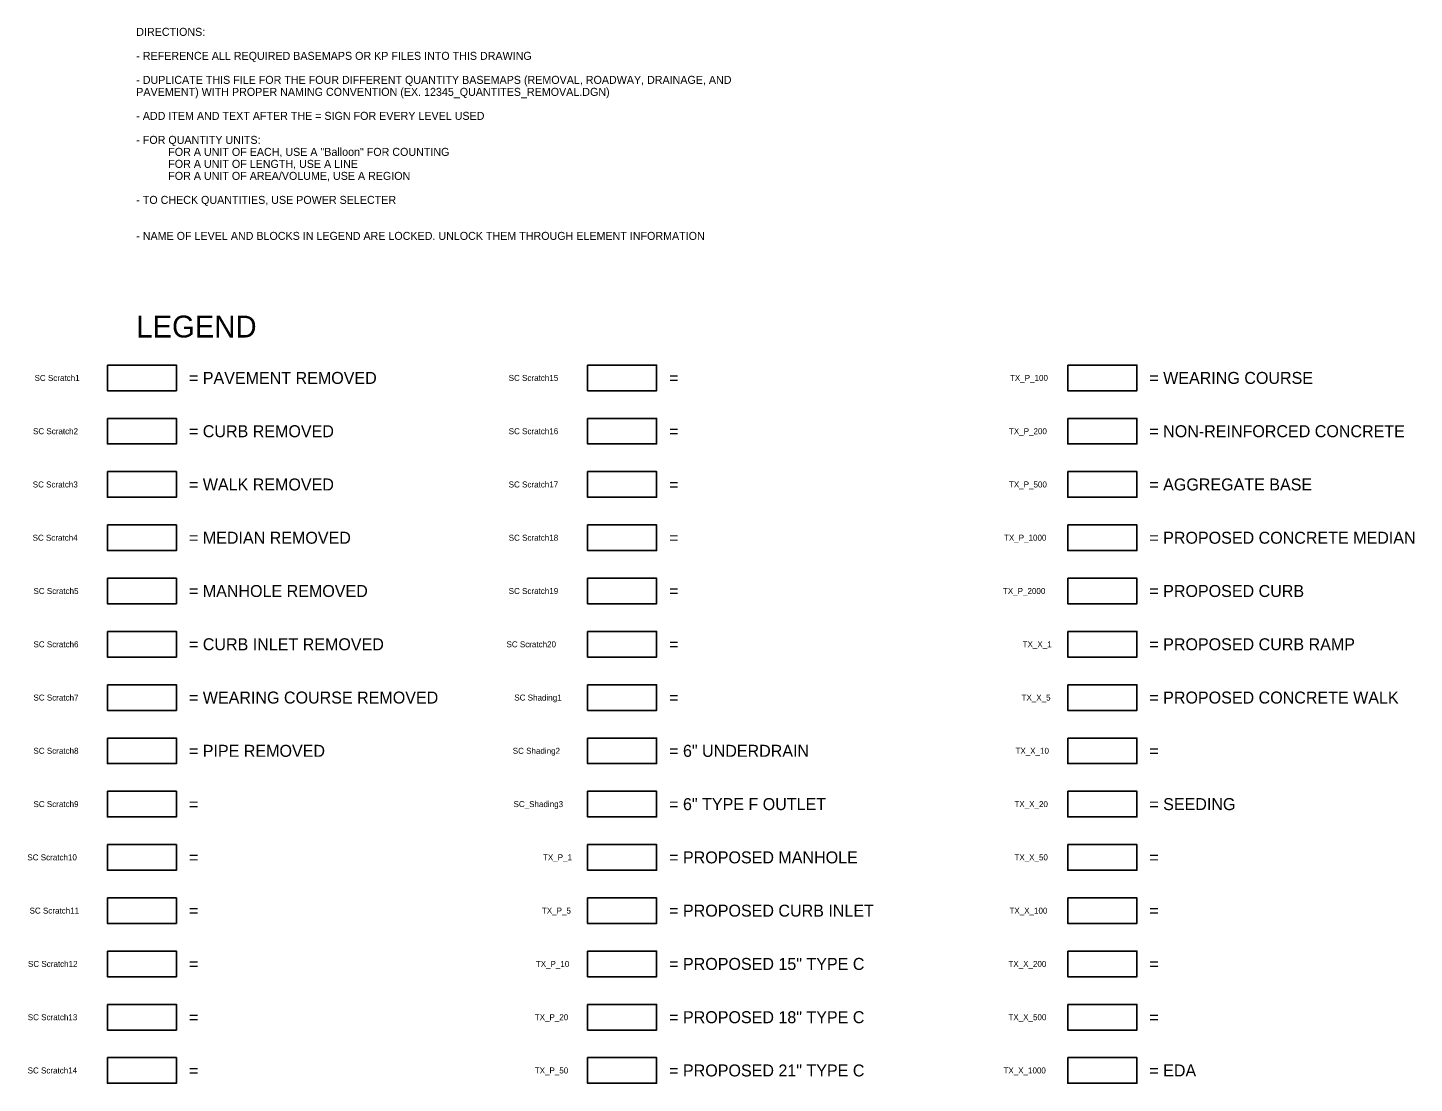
# Model space of a CAD drawing. Extents: x 2139208 to 2141645, y 639785 to 640325.
# Drawn here: x 2140935 to 2141645, y 639785 to 640325 of the extents above; entities that cross this region are included whole.
import ezdxf

# ---------------------------------------------------------------- set-up
doc = ezdxf.new("R2010")
doc.units = 0
for name, color, linetype in [('_CIVIL_CONSTRUCTION', 7, 'Continuous'), ('Default', 7, 'Continuous'), ('GE_X_Alignment', 7, 'Continuous'), ('GE_X_Alignment_100_Bearings', 7, 'Continuous'), ('GE_X_Alignment_100_Cardinal_Points', 7, 'Continuous'), ('GE_X_Alignment_100_Curve_Data', 7, 'Continuous'), ('GE_X_Alignment_100_Distances', 7, 'Continuous'), ('GE_X_Alignment_100_Stations', 7, 'Continuous'), ('PF_X_Ground_Line', 7, 'Continuous'), ('RW_X_CL', 7, 'Continuous'), ('RW_X_CL_100_Cardinal_Points', 7, 'Continuous'), ('RW_X_CL_100_Curve_Data', 7, 'Continuous'), ('RW_X_CL_100_Stations', 7, 'Continuous'), ('SC_Scratch1', 7, 'Continuous'), ('SC_Scratch10', 7, 'Continuous'), ('SC_Scratch11', 7, 'Continuous'), ('SC_Scratch12', 7, 'Continuous'), ('SC_Scratch13', 7, 'Continuous'), ('SC_Scratch14', 7, 'Continuous'), ('SC_Scratch15', 7, 'Continuous'), ('SC_Scratch16', 7, 'Continuous'), ('SC_Scratch17', 7, 'Continuous'), ('SC_Scratch18', 7, 'Continuous'), ('SC_Shading1', 7, 'Continuous'), ('TX_P_1', 7, 'Continuous'), ('TX_P_10', 7, 'Continuous'), ('TX_P_100', 7, 'Continuous'), ('TX_P_1000', 7, 'Continuous'), ('TX_P_20', 7, 'Continuous'), ('TX_P_200', 7, 'Continuous'), ('TX_P_2000', 7, 'Continuous'), ('TX_P_5', 7, 'Continuous'), ('TX_P_50', 7, 'Continuous'), ('TX_P_500', 7, 'Continuous'), ('TX_X_1', 7, 'Continuous'), ('TX_X_10', 7, 'Continuous'), ('TX_X_100', 7, 'Continuous'), ('TX_X_1000', 7, 'Continuous'), ('TX_X_20', 7, 'Continuous'), ('TX_X_200', 7, 'Continuous'), ('TX_X_5', 7, 'Continuous'), ('TX_X_50', 7, 'Continuous'), ('TX_X_500', 7, 'Continuous')]:
    doc.layers.add(name, color=color, linetype=linetype)

msp = doc.modelspace()

# ---------------------------------------------------------------- linework, layer by layer
at = {"layer": '_CIVIL_CONSTRUCTION'}
msp.add_lwpolyline([(2140976.05, 640152.46), (2141011.4, 640152.46), (2141011.4, 640139.35), (2140976.05, 640139.35)], close=True, dxfattribs=at)
at = {"layer": 'GE_X_Alignment'}
msp.add_lwpolyline([(2140976.05, 639934.31), (2141011.4, 639934.31), (2141011.4, 639921.2), (2140976.05, 639921.2)], close=True, dxfattribs=at)
at = {"layer": 'GE_X_Alignment_100_Bearings'}
msp.add_lwpolyline([(2141221.81, 639961.58), (2141257.16, 639961.58), (2141257.16, 639948.47), (2141221.81, 639948.47)], close=True, dxfattribs=at)
at = {"layer": 'GE_X_Alignment_100_Cardinal_Points'}
msp.add_lwpolyline([(2140976.05, 640070.65), (2141011.4, 640070.65), (2141011.4, 640057.54), (2140976.05, 640057.54)], close=True, dxfattribs=at)
at = {"layer": 'GE_X_Alignment_100_Curve_Data'}
msp.add_lwpolyline([(2140976.05, 640043.38), (2141011.4, 640043.38), (2141011.4, 640030.27), (2140976.05, 640030.27)], close=True, dxfattribs=at)
at = {"layer": 'GE_X_Alignment_100_Distances'}
msp.add_lwpolyline([(2141221.81, 640016.12), (2141257.16, 640016.12), (2141257.16, 640003), (2141221.81, 640003)], close=True, dxfattribs=at)
at = {"layer": 'GE_X_Alignment_100_Stations'}
msp.add_lwpolyline([(2141221.81, 639934.31), (2141257.16, 639934.31), (2141257.16, 639921.2), (2141221.81, 639921.2)], close=True, dxfattribs=at)
at = {"layer": 'PF_X_Ground_Line'}
msp.add_lwpolyline([(2141221.81, 640043.38), (2141257.16, 640043.38), (2141257.16, 640030.27), (2141221.81, 640030.27)], close=True, dxfattribs=at)
at = {"layer": 'RW_X_CL'}
msp.add_lwpolyline([(2140976.05, 640097.92), (2141011.4, 640097.92), (2141011.4, 640084.81), (2140976.05, 640084.81)], close=True, dxfattribs=at)
at = {"layer": 'RW_X_CL_100_Cardinal_Points'}
msp.add_lwpolyline([(2140976.05, 640016.12), (2141011.4, 640016.12), (2141011.4, 640003), (2140976.05, 640003)], close=True, dxfattribs=at)
at = {"layer": 'RW_X_CL_100_Curve_Data'}
msp.add_lwpolyline([(2140976.05, 639988.85), (2141011.4, 639988.85), (2141011.4, 639975.73), (2140976.05, 639975.73)], close=True, dxfattribs=at)
at = {"layer": 'RW_X_CL_100_Stations'}
msp.add_lwpolyline([(2140976.05, 639961.58), (2141011.4, 639961.58), (2141011.4, 639948.47), (2140976.05, 639948.47)], close=True, dxfattribs=at)
at = {"layer": 'SC_Scratch1'}
msp.add_lwpolyline([(2140976.05, 640125.19), (2141011.4, 640125.19), (2141011.4, 640112.08), (2140976.05, 640112.08)], close=True, dxfattribs=at)
at = {"layer": 'SC_Scratch10'}
msp.add_lwpolyline([(2140976.05, 639907.04), (2141011.4, 639907.04), (2141011.4, 639893.93), (2140976.05, 639893.93)], close=True, dxfattribs=at)
at = {"layer": 'SC_Scratch11'}
msp.add_lwpolyline([(2140976.05, 639879.77), (2141011.4, 639879.77), (2141011.4, 639866.66), (2140976.05, 639866.66)], close=True, dxfattribs=at)
at = {"layer": 'SC_Scratch12'}
msp.add_lwpolyline([(2140976.05, 639852.5), (2141011.4, 639852.5), (2141011.4, 639839.39), (2140976.05, 639839.39)], close=True, dxfattribs=at)
at = {"layer": 'SC_Scratch13'}
msp.add_lwpolyline([(2140976.05, 639825.24), (2141011.4, 639825.24), (2141011.4, 639812.12), (2140976.05, 639812.12)], close=True, dxfattribs=at)
at = {"layer": 'SC_Scratch14'}
msp.add_lwpolyline([(2140976.05, 639797.97), (2141011.4, 639797.97), (2141011.4, 639784.86), (2140976.05, 639784.86)], close=True, dxfattribs=at)
at = {"layer": 'SC_Scratch15'}
msp.add_lwpolyline([(2141221.81, 640152.46), (2141257.16, 640152.46), (2141257.16, 640139.35), (2141221.81, 640139.35)], close=True, dxfattribs=at)
at = {"layer": 'SC_Scratch16'}
msp.add_lwpolyline([(2141221.81, 640125.19), (2141257.16, 640125.19), (2141257.16, 640112.08), (2141221.81, 640112.08)], close=True, dxfattribs=at)
at = {"layer": 'SC_Scratch17'}
msp.add_lwpolyline([(2141221.81, 640097.92), (2141257.16, 640097.92), (2141257.16, 640084.81), (2141221.81, 640084.81)], close=True, dxfattribs=at)
at = {"layer": 'SC_Scratch18'}
msp.add_lwpolyline([(2141221.81, 640070.65), (2141257.16, 640070.65), (2141257.16, 640057.54), (2141221.81, 640057.54)], close=True, dxfattribs=at)
at = {"layer": 'SC_Shading1'}
msp.add_lwpolyline([(2141221.81, 639988.85), (2141257.16, 639988.85), (2141257.16, 639975.73), (2141221.81, 639975.73)], close=True, dxfattribs=at)
at = {"layer": 'TX_P_1'}
msp.add_lwpolyline([(2141221.81, 639907.04), (2141257.16, 639907.04), (2141257.16, 639893.93), (2141221.81, 639893.93)], close=True, dxfattribs=at)
at = {"layer": 'TX_P_10'}
msp.add_lwpolyline([(2141221.81, 639852.5), (2141257.16, 639852.5), (2141257.16, 639839.39), (2141221.81, 639839.39)], close=True, dxfattribs=at)
at = {"layer": 'TX_P_100'}
msp.add_lwpolyline([(2141467.57, 640152.46), (2141502.92, 640152.46), (2141502.92, 640139.35), (2141467.57, 640139.35)], close=True, dxfattribs=at)
at = {"layer": 'TX_P_1000'}
msp.add_lwpolyline([(2141467.57, 640070.65), (2141502.92, 640070.65), (2141502.92, 640057.54), (2141467.57, 640057.54)], close=True, dxfattribs=at)
at = {"layer": 'TX_P_20'}
msp.add_lwpolyline([(2141221.81, 639825.24), (2141257.16, 639825.24), (2141257.16, 639812.12), (2141221.81, 639812.12)], close=True, dxfattribs=at)
at = {"layer": 'TX_P_200'}
msp.add_lwpolyline([(2141467.57, 640125.19), (2141502.92, 640125.19), (2141502.92, 640112.08), (2141467.57, 640112.08)], close=True, dxfattribs=at)
at = {"layer": 'TX_P_2000'}
msp.add_lwpolyline([(2141467.57, 640043.38), (2141502.92, 640043.38), (2141502.92, 640030.27), (2141467.57, 640030.27)], close=True, dxfattribs=at)
at = {"layer": 'TX_P_5'}
msp.add_lwpolyline([(2141221.81, 639879.77), (2141257.16, 639879.77), (2141257.16, 639866.66), (2141221.81, 639866.66)], close=True, dxfattribs=at)
at = {"layer": 'TX_P_50'}
msp.add_lwpolyline([(2141221.81, 639797.97), (2141257.16, 639797.97), (2141257.16, 639784.86), (2141221.81, 639784.86)], close=True, dxfattribs=at)
at = {"layer": 'TX_P_500'}
msp.add_lwpolyline([(2141467.57, 640097.92), (2141502.92, 640097.92), (2141502.92, 640084.81), (2141467.57, 640084.81)], close=True, dxfattribs=at)
at = {"layer": 'TX_X_1'}
msp.add_lwpolyline([(2141467.57, 640016.12), (2141502.92, 640016.12), (2141502.92, 640003), (2141467.57, 640003)], close=True, dxfattribs=at)
at = {"layer": 'TX_X_10'}
msp.add_lwpolyline([(2141467.57, 639961.58), (2141502.92, 639961.58), (2141502.92, 639948.47), (2141467.57, 639948.47)], close=True, dxfattribs=at)
at = {"layer": 'TX_X_100'}
msp.add_lwpolyline([(2141467.57, 639879.77), (2141502.92, 639879.77), (2141502.92, 639866.66), (2141467.57, 639866.66)], close=True, dxfattribs=at)
at = {"layer": 'TX_X_1000'}
msp.add_lwpolyline([(2141467.57, 639797.97), (2141502.92, 639797.97), (2141502.92, 639784.86), (2141467.57, 639784.86)], close=True, dxfattribs=at)
at = {"layer": 'TX_X_20'}
msp.add_lwpolyline([(2141467.57, 639934.31), (2141502.92, 639934.31), (2141502.92, 639921.2), (2141467.57, 639921.2)], close=True, dxfattribs=at)
at = {"layer": 'TX_X_200'}
msp.add_lwpolyline([(2141467.57, 639852.5), (2141502.92, 639852.5), (2141502.92, 639839.39), (2141467.57, 639839.39)], close=True, dxfattribs=at)
at = {"layer": 'TX_X_5'}
msp.add_lwpolyline([(2141467.57, 639988.85), (2141502.92, 639988.85), (2141502.92, 639975.73), (2141467.57, 639975.73)], close=True, dxfattribs=at)
at = {"layer": 'TX_X_50'}
msp.add_lwpolyline([(2141467.57, 639907.04), (2141502.92, 639907.04), (2141502.92, 639893.93), (2141467.57, 639893.93)], close=True, dxfattribs=at)
at = {"layer": 'TX_X_500'}
msp.add_lwpolyline([(2141467.57, 639825.24), (2141502.92, 639825.24), (2141502.92, 639812.12), (2141467.57, 639812.12)], close=True, dxfattribs=at)

# ---------------------------------------------------------------- texts
at = {"layer": '_CIVIL_CONSTRUCTION'}
msp.add_text('SC Scratch1', height=3.072, dxfattribs=at).set_placement((2140938.76, 640144.37))
at = {"layer": 'Default'}
for s, height, p in [('DIRECTIONS:', 4.096, (2140990.82, 640321)), ('- REFERENCE ALL REQUIRED BASEMAPS OR KP FILES INTO THIS DRAWING', 4.096, (2140990.82, 640308.71)), ('- DUPLICATE THIS FILE FOR THE FOUR DIFFERENT QUANTITY BASEMAPS (REMOVAL, ROADWAY, DRAINAGE, AND ', 4.096, (2140990.82, 640296.42)), ('PAVEMENT) WITH PROPER NAMING CONVENTION (EX. 12345_QUANTITES_REMOVAL.DGN) ', 4.096, (2140990.82, 640290.28)), ('- ADD ITEM AND TEXT AFTER THE = SIGN FOR EVERY LEVEL USED', 4.096, (2140990.82, 640277.99)), ('- FOR QUANTITY UNITS:', 4.096, (2140990.82, 640265.7)), ('FOR A UNIT OF EACH, USE A "Balloon" FOR COUNTING', 4.096, (2141007.2, 640259.56)), ('FOR A UNIT OF LENGTH, USE A LINE', 4.096, (2141007.2, 640253.42)), ('FOR A UNIT OF AREA/VOLUME, USE A REGION', 4.096, (2141007.2, 640247.27)), ('- TO CHECK QUANTITIES, USE POWER SELECTER', 4.096, (2140990.82, 640234.98)), ('- NAME OF LEVEL AND BLOCKS IN LEGEND ARE LOCKED. UNLOCK THEM THROUGH ELEMENT INFORMATION', 4.096, (2140990.82, 640216.55)), ('LEGEND', 11.2, (2140990.82, 640166.59)), ('= PAVEMENT REMOVED', 6.144, (2141017.79, 640142.83)), ('= WEARING COURSE', 6.144, (2141509.31, 640142.83)), ('= ', 6.144, (2141263.55, 640142.83)), ('= CURB REMOVED', 6.144, (2141017.79, 640115.56)), ('= ', 6.144, (2141263.55, 640115.56)), ('= NON-REINFORCED CONCRETE', 6.144, (2141509.31, 640115.56)), ('= WALK REMOVED', 6.144, (2141017.79, 640088.29)), ('= ', 6.144, (2141263.55, 640088.29)), ('= AGGREGATE BASE', 6.144, (2141509.31, 640088.29)), ('= MEDIAN REMOVED', 6.144, (2141017.79, 640061.02)), ('= ', 6.144, (2141263.55, 640061.02)), ('= PROPOSED CONCRETE MEDIAN', 6.144, (2141509.31, 640061.02)), ('= MANHOLE REMOVED', 6.144, (2141017.79, 640033.76)), ('= ', 6.144, (2141263.55, 640033.76)), ('= PROPOSED CURB', 6.144, (2141509.31, 640033.76)), ('= CURB INLET REMOVED', 6.144, (2141017.79, 640006.49)), ('= PROPOSED CURB RAMP', 6.144, (2141509.31, 640006.49)), ('= ', 6.144, (2141263.55, 640006.49)), ('= WEARING COURSE REMOVED', 6.144, (2141017.79, 639979.22)), ('= PROPOSED CONCRETE WALK', 6.144, (2141509.31, 639979.22)), ('= ', 6.144, (2141263.55, 639979.22)), ('= PIPE REMOVED', 6.144, (2141017.79, 639951.95)), ('= 6" UNDERDRAIN', 6.144, (2141263.55, 639951.95)), ('= ', 6.144, (2141509.31, 639951.95)), ('= ', 6.144, (2141017.79, 639924.68)), ('= 6" TYPE F OUTLET', 6.144, (2141263.55, 639924.68)), ('= SEEDING', 6.144, (2141509.31, 639924.68)), ('= ', 6.144, (2141017.79, 639897.41)), ('= PROPOSED MANHOLE', 6.144, (2141263.55, 639897.41)), ('= ', 6.144, (2141509.31, 639897.41)), ('= ', 6.144, (2141017.79, 639870.14)), ('= PROPOSED CURB INLET', 6.144, (2141263.55, 639870.14)), ('= ', 6.144, (2141509.31, 639870.14)), ('= ', 6.144, (2141017.79, 639842.88)), ('= PROPOSED 15" TYPE C', 6.144, (2141263.55, 639842.88)), ('= ', 6.144, (2141509.31, 639842.88)), ('= PROPOSED 18" TYPE C', 6.144, (2141263.55, 639815.61)), ('= ', 6.144, (2141017.79, 639815.61)), ('= ', 6.144, (2141509.31, 639815.61)), ('= ', 6.144, (2141017.79, 639788.34)), ('= PROPOSED 21" TYPE C', 6.144, (2141263.55, 639788.34)), ('= EDA', 6.144, (2141509.31, 639788.34))]:
    msp.add_text(s, height=height, dxfattribs=at).set_placement(p)
at = {"layer": 'GE_X_Alignment'}
msp.add_text('SC Scratch9', height=3.072, dxfattribs=at).set_placement((2140938.21, 639926.22))
at = {"layer": 'GE_X_Alignment_100_Bearings'}
msp.add_text('SC Shading2', height=3.072, dxfattribs=at).set_placement((2141183.51, 639953.49))
at = {"layer": 'GE_X_Alignment_100_Cardinal_Points'}
msp.add_text('SC Scratch4', height=3.072, dxfattribs=at).set_placement((2140937.77, 640062.56))
at = {"layer": 'GE_X_Alignment_100_Curve_Data'}
msp.add_text('SC Scratch5', height=3.072, dxfattribs=at).set_placement((2140938.21, 640035.29))
at = {"layer": 'GE_X_Alignment_100_Distances'}
msp.add_text('SC Scratch20', height=3.072, dxfattribs=at).set_placement((2141180.31, 640008.02))
at = {"layer": 'GE_X_Alignment_100_Stations'}
msp.add_text('SC_Shading3', height=3.072, dxfattribs=at).set_placement((2141183.92, 639926.22))
at = {"layer": 'PF_X_Ground_Line'}
msp.add_text('SC Scratch19', height=3.072, dxfattribs=at).set_placement((2141181.43, 640035.29))
at = {"layer": 'RW_X_CL'}
msp.add_text('SC Scratch3', height=3.072, dxfattribs=at).set_placement((2140937.84, 640089.83))
at = {"layer": 'RW_X_CL_100_Cardinal_Points'}
msp.add_text('SC Scratch6', height=3.072, dxfattribs=at).set_placement((2140938.21, 640008.02))
at = {"layer": 'RW_X_CL_100_Curve_Data'}
msp.add_text('SC Scratch7', height=3.072, dxfattribs=at).set_placement((2140938.21, 639980.75))
at = {"layer": 'RW_X_CL_100_Stations'}
msp.add_text('SC Scratch8', height=3.072, dxfattribs=at).set_placement((2140938.21, 639953.49))
at = {"layer": 'SC_Scratch1'}
msp.add_text('SC Scratch2', height=3.072, dxfattribs=at).set_placement((2140937.96, 640117.1))
at = {"layer": 'SC_Scratch10'}
msp.add_text('SC Scratch10', height=3.072, dxfattribs=at).set_placement((2140935.09, 639898.95))
at = {"layer": 'SC_Scratch11'}
msp.add_text('SC Scratch11', height=3.072, dxfattribs=at).set_placement((2140936.22, 639871.68))
at = {"layer": 'SC_Scratch12'}
msp.add_text('SC Scratch12', height=3.072, dxfattribs=at).set_placement((2140935.42, 639844.41))
at = {"layer": 'SC_Scratch13'}
msp.add_text('SC Scratch13', height=3.072, dxfattribs=at).set_placement((2140935.3, 639817.14))
at = {"layer": 'SC_Scratch14'}
msp.add_text('SC Scratch14', height=3.072, dxfattribs=at).set_placement((2140935.23, 639789.88))
at = {"layer": 'SC_Scratch15'}
msp.add_text('SC Scratch15', height=3.072, dxfattribs=at).set_placement((2141181.43, 640144.37))
at = {"layer": 'SC_Scratch16'}
msp.add_text('SC Scratch16', height=3.072, dxfattribs=at).set_placement((2141181.43, 640117.1))
at = {"layer": 'SC_Scratch17'}
msp.add_text('SC Scratch17', height=3.072, dxfattribs=at).set_placement((2141181.43, 640089.83))
at = {"layer": 'SC_Scratch18'}
msp.add_text('SC Scratch18', height=3.072, dxfattribs=at).set_placement((2141181.43, 640062.56))
at = {"layer": 'SC_Shading1'}
msp.add_text('SC Shading1', height=3.072, dxfattribs=at).set_placement((2141184.31, 639980.75))
at = {"layer": 'TX_P_1'}
msp.add_text('TX_P_1', height=3.072, dxfattribs=at).set_placement((2141198.99, 639898.95))
at = {"layer": 'TX_P_10'}
msp.add_text('TX_P_10', height=3.072, dxfattribs=at).set_placement((2141195.31, 639844.41))
at = {"layer": 'TX_P_100'}
msp.add_text('TX_P_100', height=3.072, dxfattribs=at).set_placement((2141438, 640144.37))
at = {"layer": 'TX_P_1000'}
msp.add_text('TX_P_1000', height=3.072, dxfattribs=at).set_placement((2141434.93, 640062.56))
at = {"layer": 'TX_P_20'}
msp.add_text('TX_P_20', height=3.072, dxfattribs=at).set_placement((2141194.78, 639817.14))
at = {"layer": 'TX_P_200'}
msp.add_text('TX_P_200', height=3.072, dxfattribs=at).set_placement((2141437.47, 640117.1))
at = {"layer": 'TX_P_2000'}
msp.add_text('TX_P_2000', height=3.072, dxfattribs=at).set_placement((2141434.39, 640035.29))
at = {"layer": 'TX_P_5'}
msp.add_text('TX_P_5', height=3.072, dxfattribs=at).set_placement((2141198.43, 639871.68))
at = {"layer": 'TX_P_50'}
msp.add_text('TX_P_50', height=3.072, dxfattribs=at).set_placement((2141194.78, 639789.88))
at = {"layer": 'TX_P_500'}
msp.add_text('TX_P_500', height=3.072, dxfattribs=at).set_placement((2141437.47, 640089.83))
at = {"layer": 'TX_X_1'}
msp.add_text('TX_X_1', height=3.072, dxfattribs=at).set_placement((2141444.48, 640008.02))
at = {"layer": 'TX_X_10'}
msp.add_text('TX_X_10', height=3.072, dxfattribs=at).set_placement((2141440.8, 639953.49))
at = {"layer": 'TX_X_100'}
msp.add_text('TX_X_100', height=3.072, dxfattribs=at).set_placement((2141437.73, 639871.68))
at = {"layer": 'TX_X_1000'}
msp.add_text('TX_X_1000', height=3.072, dxfattribs=at).set_placement((2141434.66, 639789.88))
at = {"layer": 'TX_X_20'}
msp.add_text('TX_X_20', height=3.072, dxfattribs=at).set_placement((2141440.27, 639926.22))
at = {"layer": 'TX_X_200'}
msp.add_text('TX_X_200', height=3.072, dxfattribs=at).set_placement((2141437.2, 639844.41))
at = {"layer": 'TX_X_5'}
msp.add_text('TX_X_5', height=3.072, dxfattribs=at).set_placement((2141443.93, 639980.75))
at = {"layer": 'TX_X_50'}
msp.add_text('TX_X_50', height=3.072, dxfattribs=at).set_placement((2141440.27, 639898.95))
at = {"layer": 'TX_X_500'}
msp.add_text('TX_X_500', height=3.072, dxfattribs=at).set_placement((2141437.2, 639817.14))

doc.saveas('drawing.dxf')
